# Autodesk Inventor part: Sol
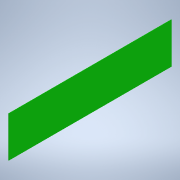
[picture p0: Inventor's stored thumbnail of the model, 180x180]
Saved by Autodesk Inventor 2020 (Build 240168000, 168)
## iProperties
Created: 2022-10
Part Number: Sol
Material: Générique
Document SubType Name: Modeling
Designer: bruno
Density: 1 g/cm^3
Appearance: Transparent - Clair
Author: bruno
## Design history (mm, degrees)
sketch "Esquisse1"
  geometry: L1 (0, 0)-(1000, 0); L2 (1000, 0)-(1000, -4000); L3 (1000, -4000)-(0, -4000); L4 (0, -4000)-(0, 0)
  constraints: 8 end point, 2 parallel, 1 horizontal, 1 perpendicular
  dimensions: "d0" = 1000 distance of L2.end L3.end; "d1" = 4000 distance of L1.end L2.end
extrude "Extrusion1" new body sketch "Esquisse1" distance "d2" = 10; taper "d3" = 0 deg
sketch "Esquisse2"
  geometry: L1 (-3773.641, 444.733)-(-3773.641, 488.483) reference; L2 (-3769.641, 491.608)-(-3773.641, 491.608) reference; C1 r 1.595 at (-3769.641, 491.608); 1 further point
  constraints: 1 centre point, 1 coincident
extrude "Extrusion2" join sketch "Esquisse2" distance "d4" = 150; taper "d5" = 0 deg
node "Solide1"
node "Référence1"
node "Référence2"
